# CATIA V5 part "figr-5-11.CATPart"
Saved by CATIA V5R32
Part number: Part1
Bounding box of the stored display mesh (mm): x 0 to 150, y -70 to 70, z -150 to 69.804
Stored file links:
  D:\PROJECTS\Project 2022\CATIA V5 6R 2022\Resources\Part Files\c05_catia_v5_6r2022_prt\figr-5-11.CATPart
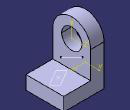
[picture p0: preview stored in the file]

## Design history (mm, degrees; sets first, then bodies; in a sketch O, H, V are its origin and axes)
Set1
  Sketch1 on face of Pad2, origin (0, 0, -100), H (1, 0, 0), V (0, 1, 0)
    point P1 (100, 0)
    coincidence: P1 H
  Sketch2 on face of Pad1, origin (50, 0, 0), H (0, 1, 0), V (0, 0, 1)
    line L1 (-40, -80) -> (40, -40)
  Plane1: type 1Line1Pt, RefPoint Sketch1, Line Sketch2
Body1 (main body)
  Sketch3 on yz-plane, origin (0, 0, 0), H (0, 1, 0), V (0, 0, 1)
    arc A1 centre (0, 0) radius 70 from (70, 0) to (-70, 0) ccw
    point P1 (70, 0)
    point P2 (-70, 0)
    line L1 (-70, 0) -> (-70, -150)
    line L2 (-70, -150) -> (70, -150)
    line L3 (70, -150) -> (70, 0)
    circle A2 centre (0, 0) radius 37.5
    radius A1 = 70
    radius A2 = 37.5
    distance O L2 = 150
    coincidence: P1 H, P2 H
    tangency: L1 A1, L3 A1
    horizontal: L2 H
  Pad1: profile Sketch3, direction (1, 0, 0), length 50
  Sketch4 on face of Pad1, origin (50, 0, 0), H (0, 1, 0), V (0, 0, 1)
    line L1 (-70, -150) -> (70, -150)
    line L2 (70, -150) -> (70, -100)
    line L3 (70, -100) -> (-70, -100)
    line L4 (-70, -100) -> (-70, -150)
    reference projected line E1 (-70, -150) -> (70, -150) from edge [face of Pad1 | face of Pad1]
    reference projected line E2 (-70, 0) -> (-70, -150) from edge [face of Pad1 | face of Pad1]
    reference projected line E3 (70, -150) -> (70, 0) from edge [face of Pad1 | face of Pad1]
    length L2 = 50
    horizontal: L1 H, L3 H
    vertical: L2 V, L4 V
    coincidence: L1 E1, E2 L4, L2 E3
  Pad2: profile Sketch4, direction (1, 0, 0), length 100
